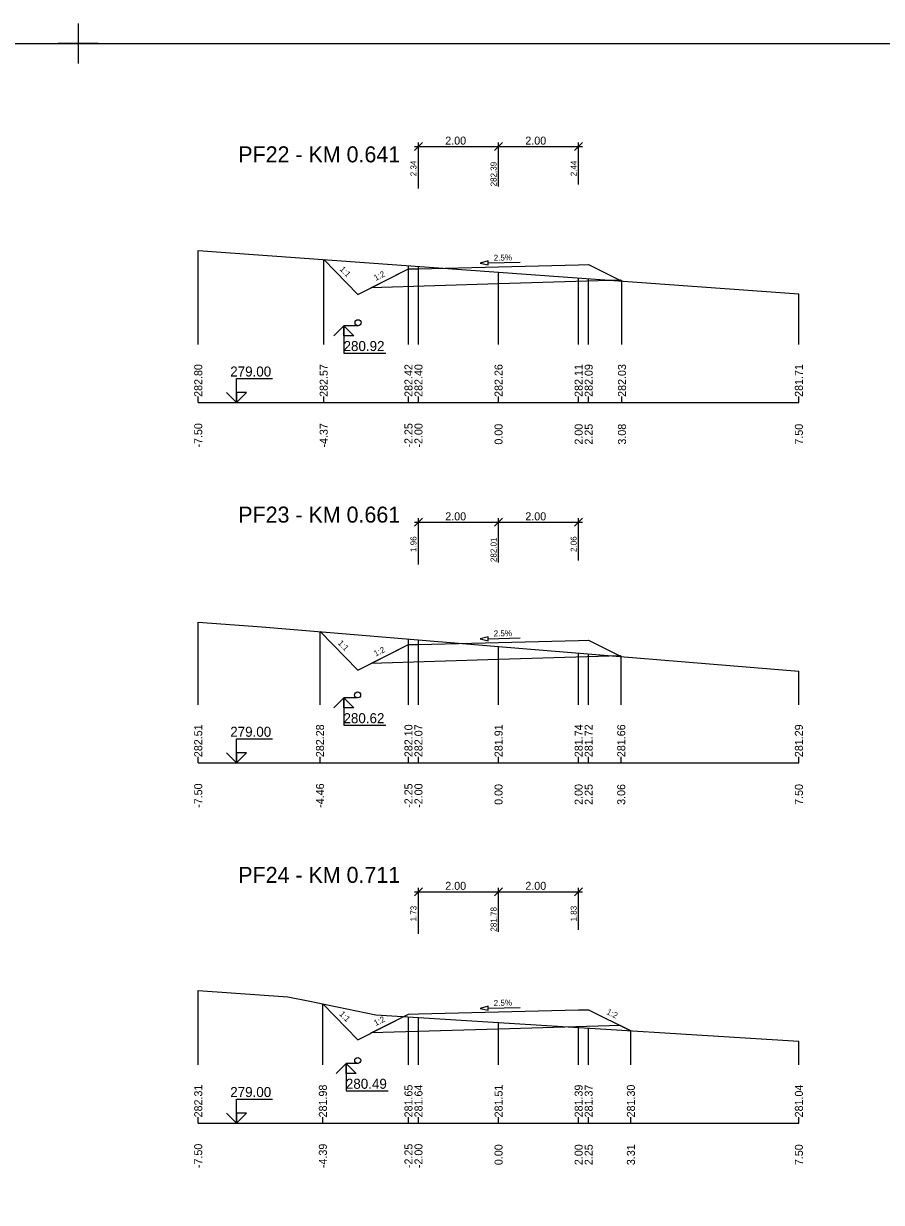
# Model space of a CAD drawing. Extents: x -5 to 1895, y -2 to 602.
# Drawn here: x 1456.4 to 1670.6, y 307.2 to 601.7 of the extents above; entities that cross this region are included whole.
import ezdxf

# ---------------------------------------------------------------- set-up
doc = ezdxf.new("R2010")
doc.units = 0
for name, color, linetype in [('KOTA', 7, 'Continuous'), ('KOTA_DELKY', 7, 'Continuous'), ('KOTA_DELKY_CONT', 7, 'Continuous'), ('KRIZENI', 7, 'Continuous'), ('NS_TELESO_VOZOVKY', 7, 'Continuous'), ('NS_V_PF', 7, 'Continuous'), ('REZY_PF_PUVODNI', 7, 'Continuous'), ('SESTAVY_REZU_PF', 7, 'Continuous'), ('SKLON', 7, 'Continuous'), ('SVK', 7, 'Continuous')]:
    doc.layers.add(name, color=color, linetype=linetype)

msp = doc.modelspace()

# ---------------------------------------------------------------- linework, layer by layer
for p, q in [((1470, 601.67), (1470, 591.67)), ((1470, 601.67), (1470, 591.67)), ((1470, 601.67), (1470, 591.67)), ((1470, 601.67), (1470, 591.67)), ((1470, 601.67), (1470, 591.67)), ((1470, 601.67), (1470, 591.67)), ((1470, 601.67), (1470, 591.67)), ((1470, 601.67), (1470, 591.67)), ((1470, 601.67), (1470, 591.67)), ((1470, 601.67), (1470, 591.67)), ((1470, 601.67), (1470, 591.67)), ((1470, 601.67), (1470, 591.67)), ((1470, 601.67), (1470, 591.67)), ((1470, 601.67), (1470, 591.67)), ((1470, 601.67), (1470, 591.67)), ((1470, 601.67), (1470, 591.67)), ((1470, 601.67), (1470, 591.67)), ((1470, 601.67), (1470, 591.67)), ((1470, 601.67), (1470, 591.67)), ((1470, 601.67), (1470, 591.67)), ((1470, 601.67), (1470, 591.67)), ((1470, 601.67), (1470, 591.67)), ((1470, 601.67), (1470, 591.67)), ((1470, 601.67), (1470, 591.67)), ((1470, 601.67), (1470, 591.67)), ((1470, 601.67), (1470, 591.67)), ((1470, 601.67), (1470, 591.67)), ((1470, 601.67), (1470, 591.67)), ((1470, 601.67), (1470, 591.67)), ((1470, 601.67), (1470, 591.67)), ((1470, 601.67), (1470, 591.67)), ((1470, 601.67), (1470, 591.67)), ((1470, 601.67), (1470, 591.67)), ((1470, 601.67), (1470, 591.67)), ((1470, 601.67), (1470, 591.67)), ((1470, 601.67), (1470, 591.67)), ((1470, 601.67), (1470, 591.67)), ((1470, 601.67), (1470, 591.67)), ((1470, 601.67), (1470, 591.67)), ((1470, 601.67), (1470, 591.67)), ((1470, 601.67), (1470, 591.67)), ((1470, 601.67), (1470, 591.67)), ((1470, 601.67), (1470, 591.67)), ((1470, 601.67), (1470, 591.67)), ((1470, 601.67), (1470, 591.67)), ((1470, 601.67), (1470, 591.67)), ((1470, 601.67), (1470, 591.67)), ((1470, 601.67), (1470, 591.67)), ((1470, 601.67), (1470, 591.67)), ((1470, 601.67), (1470, 591.67)), ((1470, 601.67), (1470, 591.67)), ((1470, 601.67), (1470, 591.67)), ((1470, 601.67), (1470, 591.67)), ((1470, 601.67), (1470, 591.67)), ((1475, 596.67), (1465, 596.67)), ((1475, 596.67), (1465, 596.67)), ((1475, 596.67), (1465, 596.67)), ((1475, 596.67), (1465, 596.67)), ((1475, 596.67), (1465, 596.67)), ((1475, 596.67), (1465, 596.67)), ((1475, 596.67), (1465, 596.67)), ((1475, 596.67), (1465, 596.67)), ((1475, 596.67), (1465, 596.67)), ((1475, 596.67), (1465, 596.67)), ((1475, 596.67), (1465, 596.67)), ((1475, 596.67), (1465, 596.67)), ((1475, 596.67), (1465, 596.67)), ((1475, 596.67), (1465, 596.67)), ((1475, 596.67), (1465, 596.67)), ((1475, 596.67), (1465, 596.67)), ((1475, 596.67), (1465, 596.67)), ((1475, 596.67), (1465, 596.67)), ((1475, 596.67), (1465, 596.67)), ((1475, 596.67), (1465, 596.67)), ((1475, 596.67), (1465, 596.67)), ((1475, 596.67), (1465, 596.67)), ((1475, 596.67), (1465, 596.67)), ((1475, 596.67), (1465, 596.67)), ((1475, 596.67), (1465, 596.67)), ((1475, 596.67), (1465, 596.67)), ((1475, 596.67), (1465, 596.67)), ((1475, 596.67), (1465, 596.67)), ((1475, 596.67), (1465, 596.67)), ((1475, 596.67), (1465, 596.67)), ((1475, 596.67), (1465, 596.67)), ((1475, 596.67), (1465, 596.67)), ((1475, 596.67), (1465, 596.67)), ((1475, 596.67), (1465, 596.67)), ((1475, 596.67), (1465, 596.67)), ((1475, 596.67), (1465, 596.67)), ((1475, 596.67), (1465, 596.67)), ((1475, 596.67), (1465, 596.67)), ((1475, 596.67), (1465, 596.67)), ((1475, 596.67), (1465, 596.67)), ((1475, 596.67), (1465, 596.67)), ((1475, 596.67), (1465, 596.67)), ((1475, 596.67), (1465, 596.67)), ((1475, 596.67), (1465, 596.67)), ((1475, 596.67), (1465, 596.67)), ((1475, 596.67), (1465, 596.67)), ((1475, 596.67), (1465, 596.67)), ((1475, 596.67), (1465, 596.67)), ((1475, 596.67), (1465, 596.67)), ((1475, 596.67), (1465, 596.67)), ((1475, 596.67), (1465, 596.67)), ((1475, 596.67), (1465, 596.67)), ((1475, 596.67), (1465, 596.67)), ((1475, 596.67), (1465, 596.67))]:
    msp.add_line(p, q)
msp.add_lwpolyline([(0, 596.67), (1890, 596.67), (1890, 2.67), (0, 2.67)], close=True)
at = {"layer": 'KOTA'}
for points in [[(1536.33, 526.18), (1533.83, 523.68), (1536.33, 526.18), (1536.33, 519.36), (1546.87, 519.36)], [(1539.91, 526.18), (1536.33, 526.18)], [(1536.33, 526.18), (1538.83, 523.68), (1536.33, 523.68), (1536.33, 526.18)], [(1536.33, 526.18), (1538.83, 523.68), (1536.33, 523.68)], [(1509.57, 507), (1507.07, 509.5), (1509.57, 507), (1509.57, 513), (1518.57, 513)], [(1509.57, 507), (1512.07, 509.5), (1509.57, 509.5), (1509.57, 507)], [(1509.57, 507), (1512.07, 509.5), (1509.57, 509.5)], [(1536.32, 433.21), (1533.82, 430.71), (1536.32, 433.21), (1536.32, 426.39), (1546.86, 426.39)], [(1539.79, 433.21), (1536.32, 433.21)], [(1536.32, 433.21), (1538.82, 430.71), (1536.32, 430.71), (1536.32, 433.21)], [(1536.32, 433.21), (1538.82, 430.71), (1536.32, 430.71)], [(1509.57, 417), (1507.07, 419.5), (1509.57, 417), (1509.57, 423), (1518.57, 423)], [(1509.57, 417), (1512.07, 419.5), (1509.57, 419.5), (1509.57, 417)], [(1509.57, 417), (1512.07, 419.5), (1509.57, 419.5)], [(1536.91, 341.88), (1534.41, 339.38), (1536.91, 341.88), (1536.91, 335.06), (1547.46, 335.06)], [(1539.83, 341.88), (1536.91, 341.88)], [(1536.91, 341.88), (1539.41, 339.38), (1536.91, 339.38), (1536.91, 341.88)], [(1536.91, 341.88), (1539.41, 339.38), (1536.91, 339.38)], [(1509.57, 327), (1507.07, 329.5), (1509.57, 327), (1509.57, 333), (1518.57, 333)], [(1509.57, 327), (1512.07, 329.5), (1509.57, 329.5), (1509.57, 327)], [(1509.57, 327), (1512.07, 329.5), (1509.57, 329.5)]]:
    msp.add_lwpolyline(points, dxfattribs=at)
at = {"layer": 'KOTA_DELKY'}
for points in [[(1554, 569.93), (1556, 571.93)], [(1555, 560.43), (1555, 571.93)], [(1574, 569.93), (1576, 571.93)], [(1574, 569.93), (1576, 571.93)], [(1575, 560.93), (1575, 571.93)], [(1575, 560.93), (1575, 571.93)], [(1594, 569.93), (1596, 571.93)], [(1595, 561.43), (1595, 571.93)], [(1554, 570.93), (1576, 570.93)], [(1574, 570.93), (1596, 570.93)], [(1554, 476.07), (1556, 478.07)], [(1555, 466.57), (1555, 478.07)], [(1574, 476.07), (1576, 478.07)], [(1574, 476.07), (1576, 478.07)], [(1575, 467.07), (1575, 478.07)], [(1575, 467.07), (1575, 478.07)], [(1594, 476.07), (1596, 478.07)], [(1595, 467.57), (1595, 478.07)], [(1554, 477.07), (1576, 477.07)], [(1574, 477.07), (1596, 477.07)], [(1554, 383.76), (1556, 385.76)], [(1554, 384.76), (1576, 384.76)], [(1555, 374.26), (1555, 385.76)], [(1574, 383.76), (1576, 385.76)], [(1574, 383.76), (1576, 385.76)], [(1574, 384.76), (1596, 384.76)], [(1575, 374.76), (1575, 385.76)], [(1575, 374.76), (1575, 385.76)], [(1594, 383.76), (1596, 385.76)], [(1595, 375.26), (1595, 385.76)]]:
    msp.add_lwpolyline(points, dxfattribs=at)
at = {"layer": 'KRIZENI'}
for centre in [(1539.91, 526.93), (1539.79, 433.96), (1539.83, 342.63)]:
    msp.add_circle(centre, 0.75, dxfattribs=at)
at = {"layer": 'NS_TELESO_VOZOVKY'}
for points in [[(1575, 540.93), (1595, 541.43), (1597.5, 541.49), (1605.82, 537.33), (1605.4, 537.54), (1575, 536.63), (1543.2, 535.67), (1552.5, 540.36), (1555, 540.43), (1575, 540.93)], [(1575, 447.07), (1595, 447.57), (1597.5, 447.63), (1605.64, 443.56), (1605.4, 443.68), (1575, 442.77), (1543.2, 441.81), (1552.5, 446.51), (1555, 446.57), (1575, 447.07)], [(1575, 354.76), (1595, 355.26), (1597.5, 355.32), (1608.05, 350.04), (1605.4, 351.37), (1575, 350.46), (1543.2, 349.5), (1552.5, 354.2), (1555, 354.26), (1575, 354.76)]]:
    msp.add_lwpolyline(points, dxfattribs=at)
at = {"layer": 'NS_V_PF'}
for points in [[(1531.33, 542.7), (1539.87, 533.99), (1552.5, 540.36), (1555, 540.43), (1575, 540.93), (1595, 541.43), (1597.5, 541.49), (1605.82, 537.33)], [(1530.41, 449.78), (1539.87, 440.13), (1552.5, 446.51), (1555, 446.57), (1575, 447.07), (1595, 447.57), (1597.5, 447.63), (1605.64, 443.56)], [(1531.12, 356.75), (1539.87, 347.82), (1552.5, 354.2), (1555, 354.26), (1575, 354.76), (1595, 355.26), (1597.5, 355.32), (1608.05, 350.04)]]:
    msp.add_lwpolyline(points, dxfattribs=at)
at = {"layer": 'REZY_PF_PUVODNI'}
for points in [[(1500, 544.96), (1575, 539.55), (1650, 534.15)], [(1500, 452.12), (1515.89, 450.98), (1575, 446.09), (1650, 439.89)], [(1500, 360.07), (1522.34, 358.55), (1527.46, 357.5), (1544.38, 354.03), (1575, 352.11), (1650, 347.42)]]:
    msp.add_lwpolyline(points, dxfattribs=at)
at = {"layer": 'SESTAVY_REZU_PF'}
for points in [[(1500, 507), (1650, 507)], [(1500, 417), (1650, 417)], [(1500, 327), (1650, 327)]]:
    msp.add_lwpolyline(points, dxfattribs=at)
at = {"layer": 'SKLON'}
for points in [[(1572.39, 542.36), (1570.4, 541.81), (1572.41, 541.36)], [(1572.39, 448.5), (1570.4, 447.95), (1572.41, 447.5)], [(1572.39, 356.19), (1570.4, 355.64), (1572.41, 355.19)]]:
    msp.add_lwpolyline(points, close=True, dxfattribs=at)
for points in [[(1572.39, 542.36), (1570.4, 541.81), (1572.41, 541.36), (1572.39, 542.36)], [(1572.4, 541.86), (1580.4, 542.06)], [(1572.39, 448.5), (1570.4, 447.95), (1572.41, 447.5), (1572.39, 448.5)], [(1572.4, 448), (1580.4, 448.2)], [(1572.39, 356.19), (1570.4, 355.64), (1572.41, 355.19), (1572.39, 356.19)], [(1572.4, 355.69), (1580.4, 355.89)]]:
    msp.add_lwpolyline(points, dxfattribs=at)
at = {"layer": 'SVK'}
for points in [[(1500, 521.5), (1500, 544.96)], [(1531.33, 521.5), (1531.33, 542.7)], [(1552.5, 521.5), (1552.5, 541.17)], [(1555, 521.5), (1555, 540.99)], [(1575, 521.5), (1575, 539.55)], [(1595, 521.5), (1595, 538.11)], [(1597.5, 521.5), (1597.5, 537.93)], [(1605.82, 521.5), (1605.82, 537.33)], [(1650, 521.5), (1650, 534.15)], [(1500, 507), (1500, 508.5)], [(1531.33, 507), (1531.33, 508.5)], [(1552.5, 507), (1552.5, 508.5)], [(1555, 507), (1555, 508.5)], [(1575, 507), (1575, 508.5)], [(1595, 507), (1595, 508.5)], [(1597.5, 507), (1597.5, 508.5)], [(1605.82, 507), (1605.82, 508.5)], [(1650, 507), (1650, 508.5)], [(1500, 431.5), (1500, 452.12)], [(1530.41, 431.5), (1530.41, 449.78)], [(1552.5, 431.5), (1552.5, 447.95)], [(1555, 431.5), (1555, 447.75)], [(1575, 431.5), (1575, 446.09)], [(1595, 431.5), (1595, 444.44)], [(1597.5, 431.5), (1597.5, 444.23)], [(1605.64, 431.5), (1605.64, 443.56)], [(1650, 431.5), (1650, 439.89)], [(1500, 417), (1500, 418.5)], [(1530.41, 417), (1530.41, 418.5)], [(1552.5, 417), (1552.5, 418.5)], [(1555, 417), (1555, 418.5)], [(1575, 417), (1575, 418.5)], [(1595, 417), (1595, 418.5)], [(1597.5, 417), (1597.5, 418.5)], [(1605.64, 417), (1605.64, 418.5)], [(1650, 417), (1650, 418.5)], [(1500, 341.5), (1500, 360.07)], [(1531.12, 341.5), (1531.12, 356.75)], [(1552.5, 341.5), (1552.5, 353.52)], [(1555, 341.5), (1555, 353.36)], [(1575, 341.5), (1575, 352.11)], [(1595, 341.5), (1595, 350.86)], [(1597.5, 341.5), (1597.5, 350.7)], [(1608.05, 341.5), (1608.05, 350.04)], [(1650, 341.5), (1650, 347.42)], [(1500, 327), (1500, 328.5)], [(1531.12, 327), (1531.12, 328.5)], [(1552.5, 327), (1552.5, 328.5)], [(1555, 327), (1555, 328.5)], [(1575, 327), (1575, 328.5)], [(1595, 327), (1595, 328.5)], [(1597.5, 327), (1597.5, 328.5)], [(1608.05, 327), (1608.05, 328.5)], [(1650, 327), (1650, 328.5)]]:
    msp.add_lwpolyline(points, dxfattribs=at)

# ---------------------------------------------------------------- texts
at = {"layer": 'KOTA'}
for s, p in [('280.92', (1536.29, 519.86)), ('279.00', (1507.99, 513.5)), ('280.62', (1536.27, 426.89)), ('279.00', (1507.99, 423.5)), ('279.00', (1507.99, 333.5)), ('280.49', (1536.87, 335.56))]:
    msp.add_text(s, height=2.5, dxfattribs=at).set_placement(p)
at = {"layer": 'KOTA_DELKY'}
for p in [(1561.69, 571.43), (1581.69, 571.43), (1561.69, 477.57), (1581.69, 477.57), (1561.69, 385.26), (1581.69, 385.26)]:
    msp.add_text('2.00', height=2, dxfattribs=at).set_placement(p)
at = {"layer": 'KOTA_DELKY_CONT'}
for s, p in [('2.34', (1554.5, 563.52)), ('282.39', (1574.5, 561)), ('2.44', (1594.5, 563.52)), ('1.96', (1554.5, 469.66)), ('282.01', (1574.5, 467.14)), ('2.06', (1594.5, 469.66)), ('1.73', (1554.5, 377.35)), ('281.78', (1574.5, 374.83)), ('1.83', (1594.5, 377.35))]:
    msp.add_text(s, height=1.5, rotation=90, dxfattribs=at).set_placement(p)
at = {"layer": 'SESTAVY_REZU_PF'}
for s, p in [('PF22 - KM 0.641', (1510, 567)), ('PF23 - KM 0.661', (1510, 477)), ('PF24 - KM 0.711', (1510, 387))]:
    msp.add_text(s, height=4, dxfattribs=at).set_placement(p)
at = {"layer": 'SKLON'}
for s, rotation, p in [('2.5%', 1.4321, (1573.8, 542.4)), ('1:1', 314.4213, (1535.21, 540.17)), ('1:2', 26.7649, (1544.32, 537.36)), ('2.5%', 1.4321, (1573.8, 448.54)), ('1:1', 314.4213, (1534.75, 446.78)), ('1:2', 26.7649, (1544.32, 443.5)), ('2.5%', 1.4321, (1573.8, 356.23)), ('1:1', 314.4213, (1535.1, 354.11)), ('1:2', 26.7649, (1544.32, 351.19)), ('1:2', 333.4349, (1601.81, 354.28))]:
    msp.add_text(s, height=1.5, rotation=rotation, dxfattribs=at).set_placement(p)
at = {"layer": 'SVK'}
for s, p in [(' 282.80', (1501, 507.67)), (' 282.57', (1532.33, 507.67)), (' 282.42', (1553.5, 507.67)), (' 282.40', (1556, 507.67)), (' 282.26', (1576, 507.67)), (' 282.11', (1596, 507.67)), (' 282.09', (1598.5, 507.67)), (' 282.03', (1606.82, 507.67)), (' 281.71', (1651, 507.67)), (' -7.50', (1501, 495)), (' -4.37', (1532.33, 495)), (' -2.25', (1553.5, 495)), (' -2.00', (1556, 495)), ('  0.00', (1576, 495)), ('  2.00', (1596, 495)), ('  2.25', (1598.5, 495)), ('  3.08', (1606.82, 495)), ('  7.50', (1651, 495)), (' 282.51', (1501, 417.67)), (' 282.28', (1531.41, 417.67)), (' 282.10', (1553.5, 417.67)), (' 282.07', (1556, 417.67)), (' 281.91', (1576, 417.67)), (' 281.74', (1596, 417.67)), (' 281.72', (1598.5, 417.67)), (' 281.66', (1606.64, 417.67)), (' 281.29', (1651, 417.67)), (' -7.50', (1501, 405)), (' -4.46', (1531.41, 405)), (' -2.25', (1553.5, 405)), (' -2.00', (1556, 405)), ('  0.00', (1576, 405)), ('  2.00', (1596, 405)), ('  2.25', (1598.5, 405)), ('  3.06', (1606.64, 405)), ('  7.50', (1651, 405)), (' 282.31', (1501, 327.67)), (' 281.98', (1532.12, 327.67)), (' 281.65', (1553.5, 327.67)), (' 281.64', (1556, 327.67)), (' 281.51', (1576, 327.67)), (' 281.39', (1596, 327.67)), (' 281.37', (1598.5, 327.67)), (' 281.30', (1609.05, 327.67)), (' 281.04', (1651, 327.67)), (' -7.50', (1501, 315)), (' -4.39', (1532.12, 315)), (' -2.25', (1553.5, 315)), (' -2.00', (1556, 315)), ('  0.00', (1576, 315)), ('  2.00', (1596, 315)), ('  2.25', (1598.5, 315)), ('  3.31', (1609.05, 315)), ('  7.50', (1651, 315))]:
    msp.add_text(s, height=2, rotation=90, dxfattribs=at).set_placement(p)

doc.saveas('drawing.dxf')
